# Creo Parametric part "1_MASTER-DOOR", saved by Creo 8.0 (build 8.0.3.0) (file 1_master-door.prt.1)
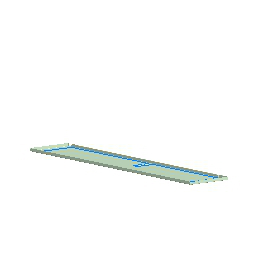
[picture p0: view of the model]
Units: millimeter Newton Second (mmNs); MM, TONNE, SECS

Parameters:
  SMT_DFLT_BEND_REL_LENGTH_TYPE = "Through All"

Other parameters: SMT_THICKNESS, SMT_PART_BEND_ALLOWANCE_FACTOR, SMT_DFLT_BEND_RADIUS, SMT_DFLT_BEND_ANGLE, SMT_DFLT_CRNR_REL_WIDTH, SMT_DFLT_CRNR_REL_DEPTH, SMT_DFLT_BEND_REL_WIDTH, SMT_DFLT_BEND_REL_DEPTH, SMT_DFLT_BEND_REL_LENGTH, SMT_DFLT_BEND_REL_ANGLE, SMT_GAP, SMT_DFLT_EDGE_TREA_WIDTH, SMT_DFLT_MITER_CUT_WIDTH, SMT_DFLT_MITER_CUT_OFFSET

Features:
  1. datum plane "DTM1"
  2. datum plane "DTM2"
  3. datum plane "DTM3"
  4. coordinate system
  5. datum plane "DTM5"
  6. datum plane "DTM6"
  7. datum plane "DTM7"
  8. protrusion
  9. round
  10. cut
  11. datum plane "DTM8"
  12. datum plane "DTM9"
  13. cut
  14. cut
  15. cut
  16. cut
  17. cut
  18. cut
  19. curve
  20. round

Other named items: HEM_585, CS0

Layers: 0_ALL_AXIS, 0_ALL_CSYS, 0_ALL_CURVES, 0_ALL_PLANES, 0_ALL_POINTS, 0_ALL_SURFS, MASTER-DOOR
